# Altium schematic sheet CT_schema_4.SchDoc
size 527 x 503 mm
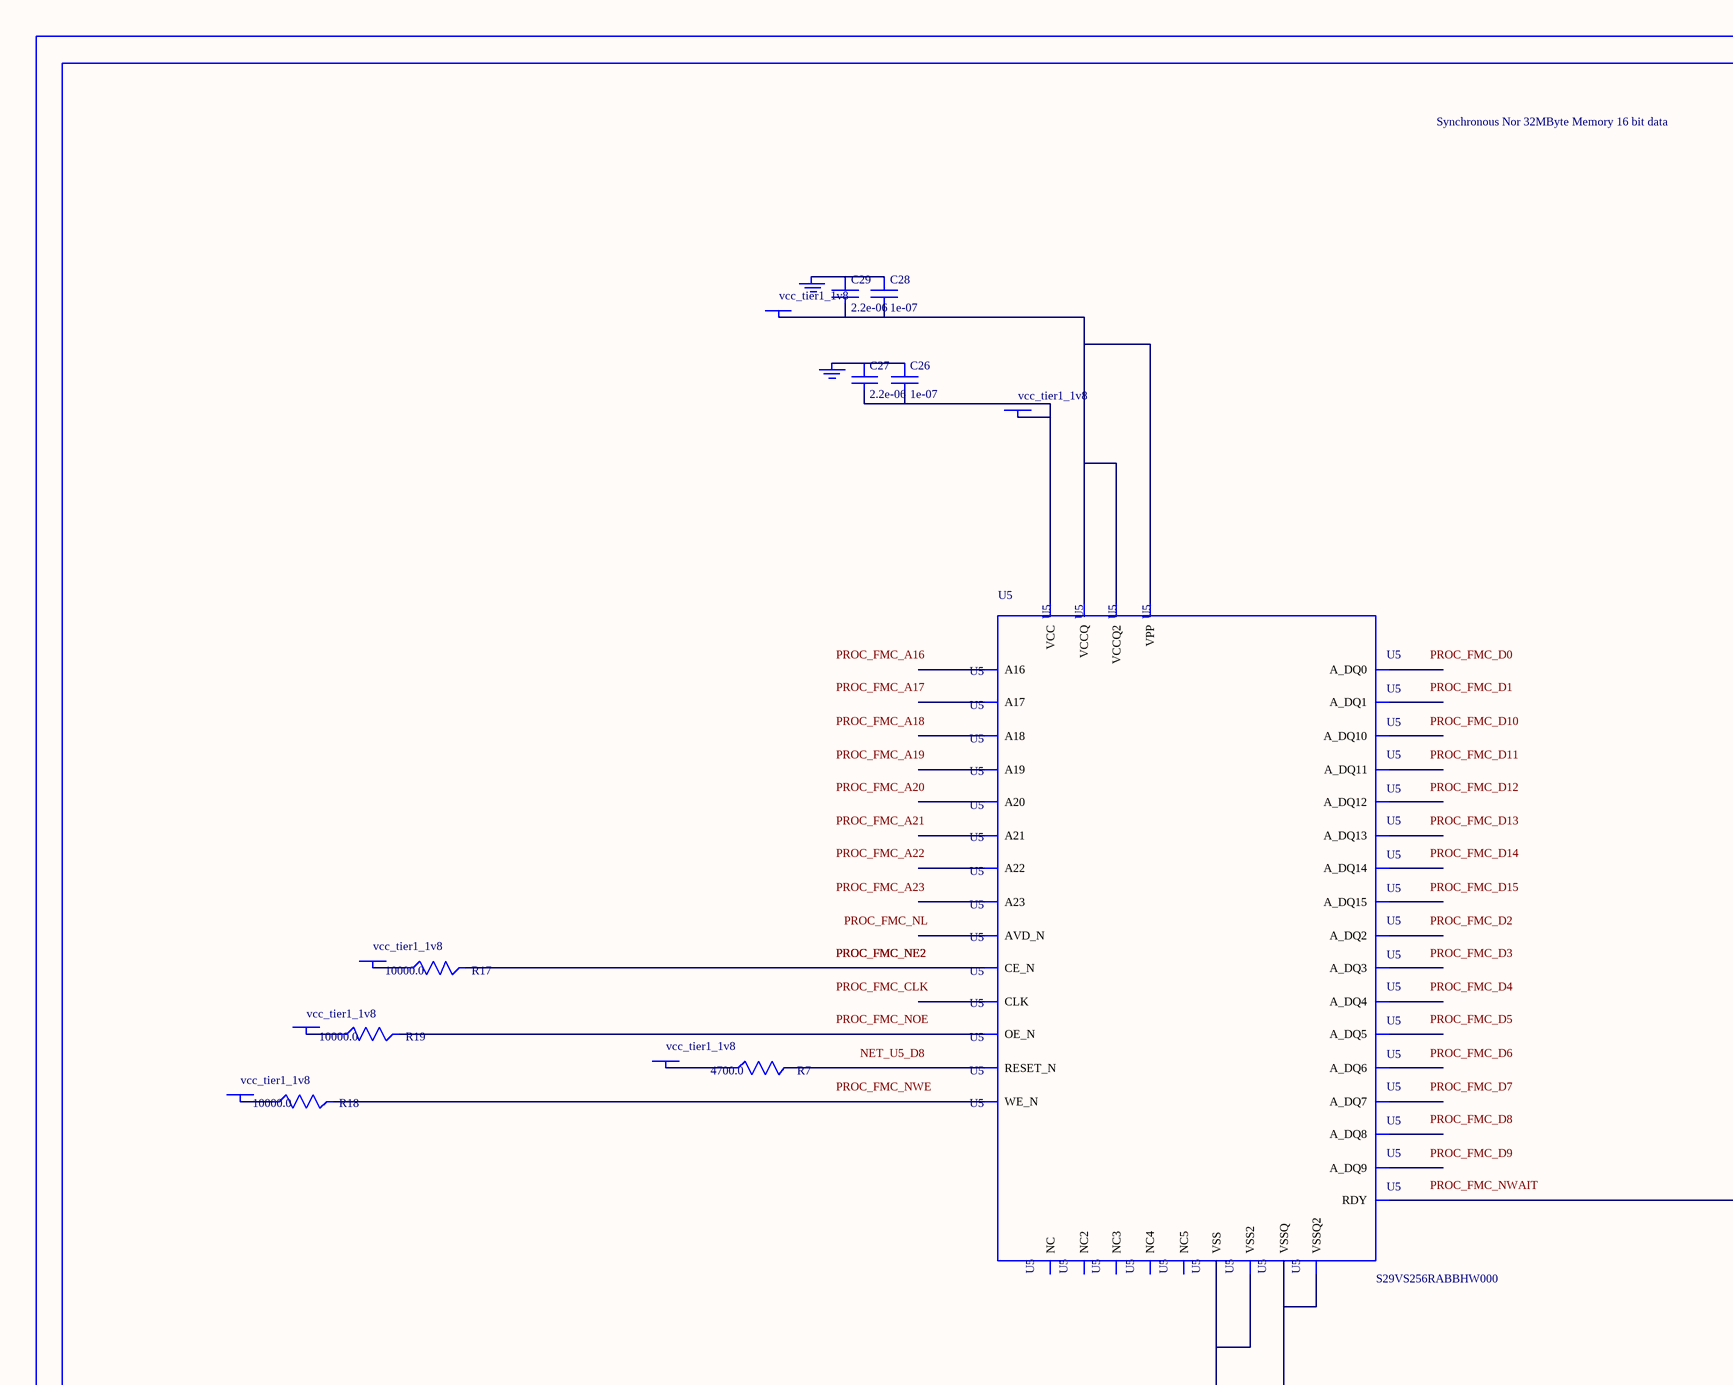
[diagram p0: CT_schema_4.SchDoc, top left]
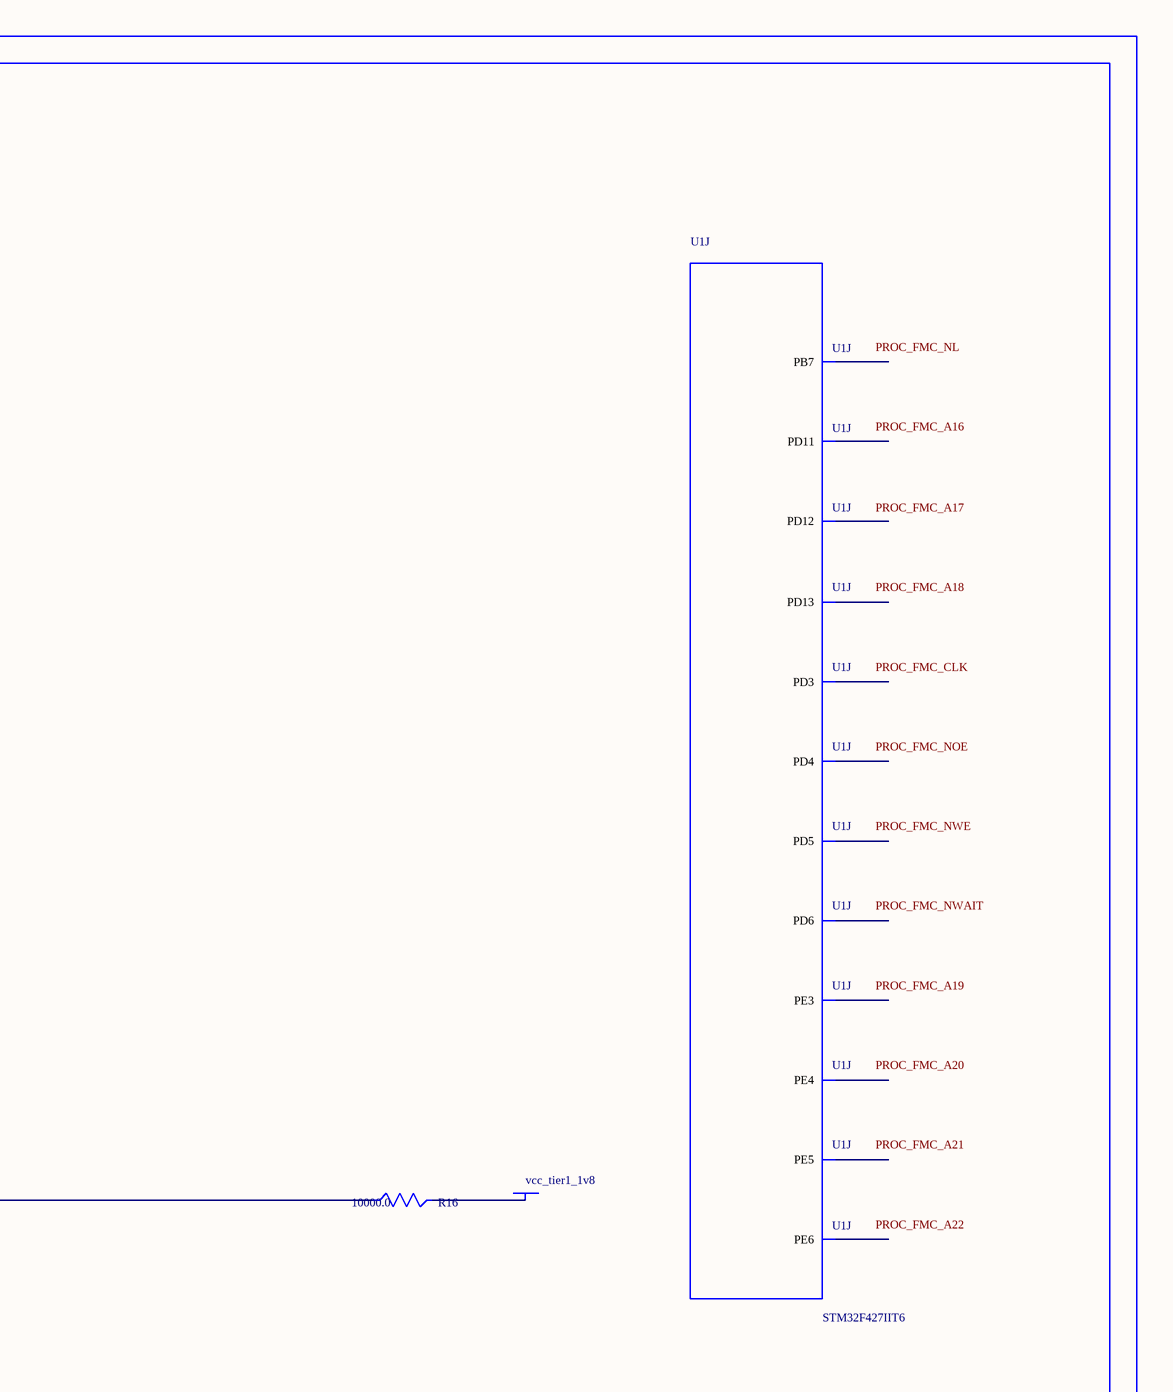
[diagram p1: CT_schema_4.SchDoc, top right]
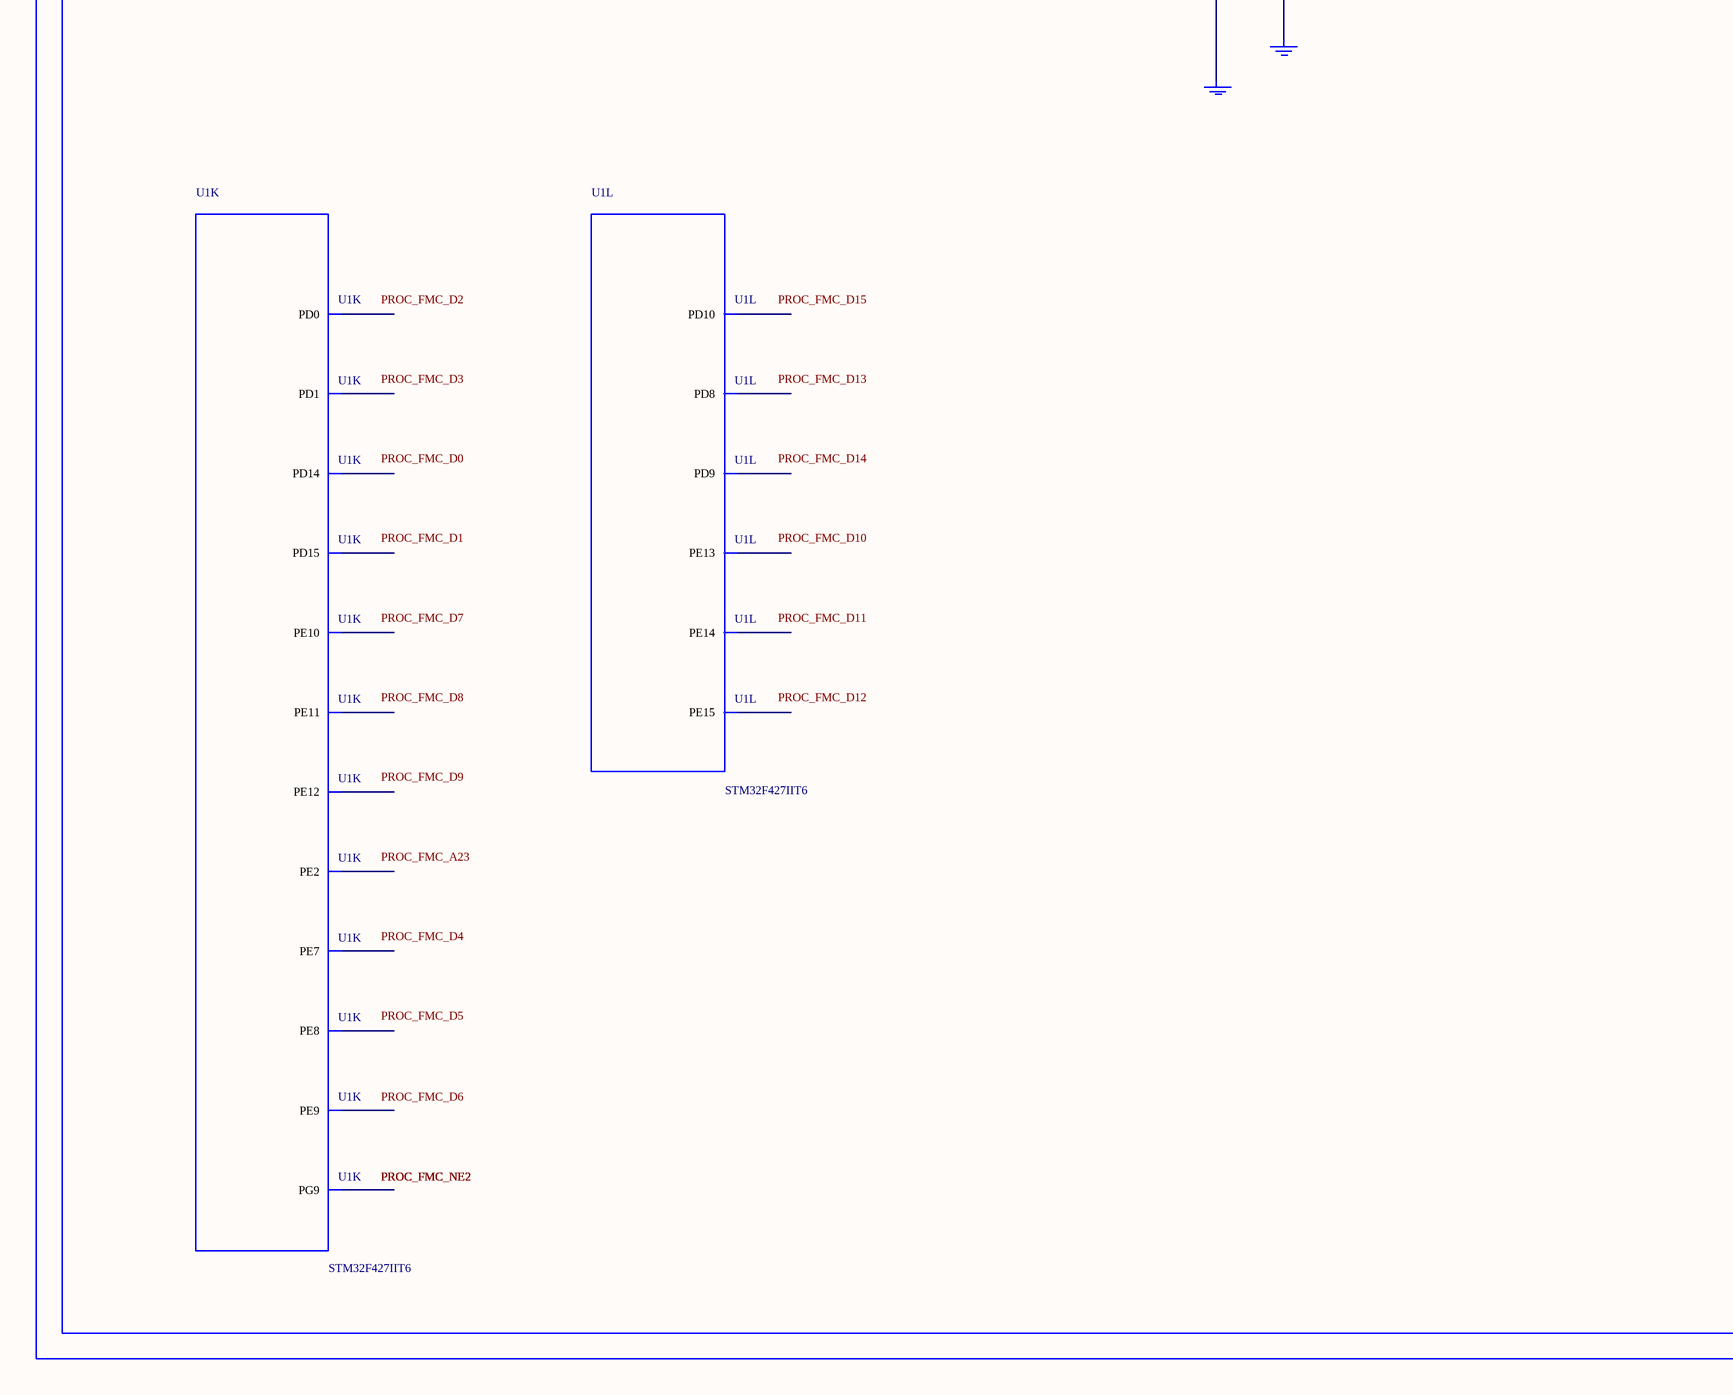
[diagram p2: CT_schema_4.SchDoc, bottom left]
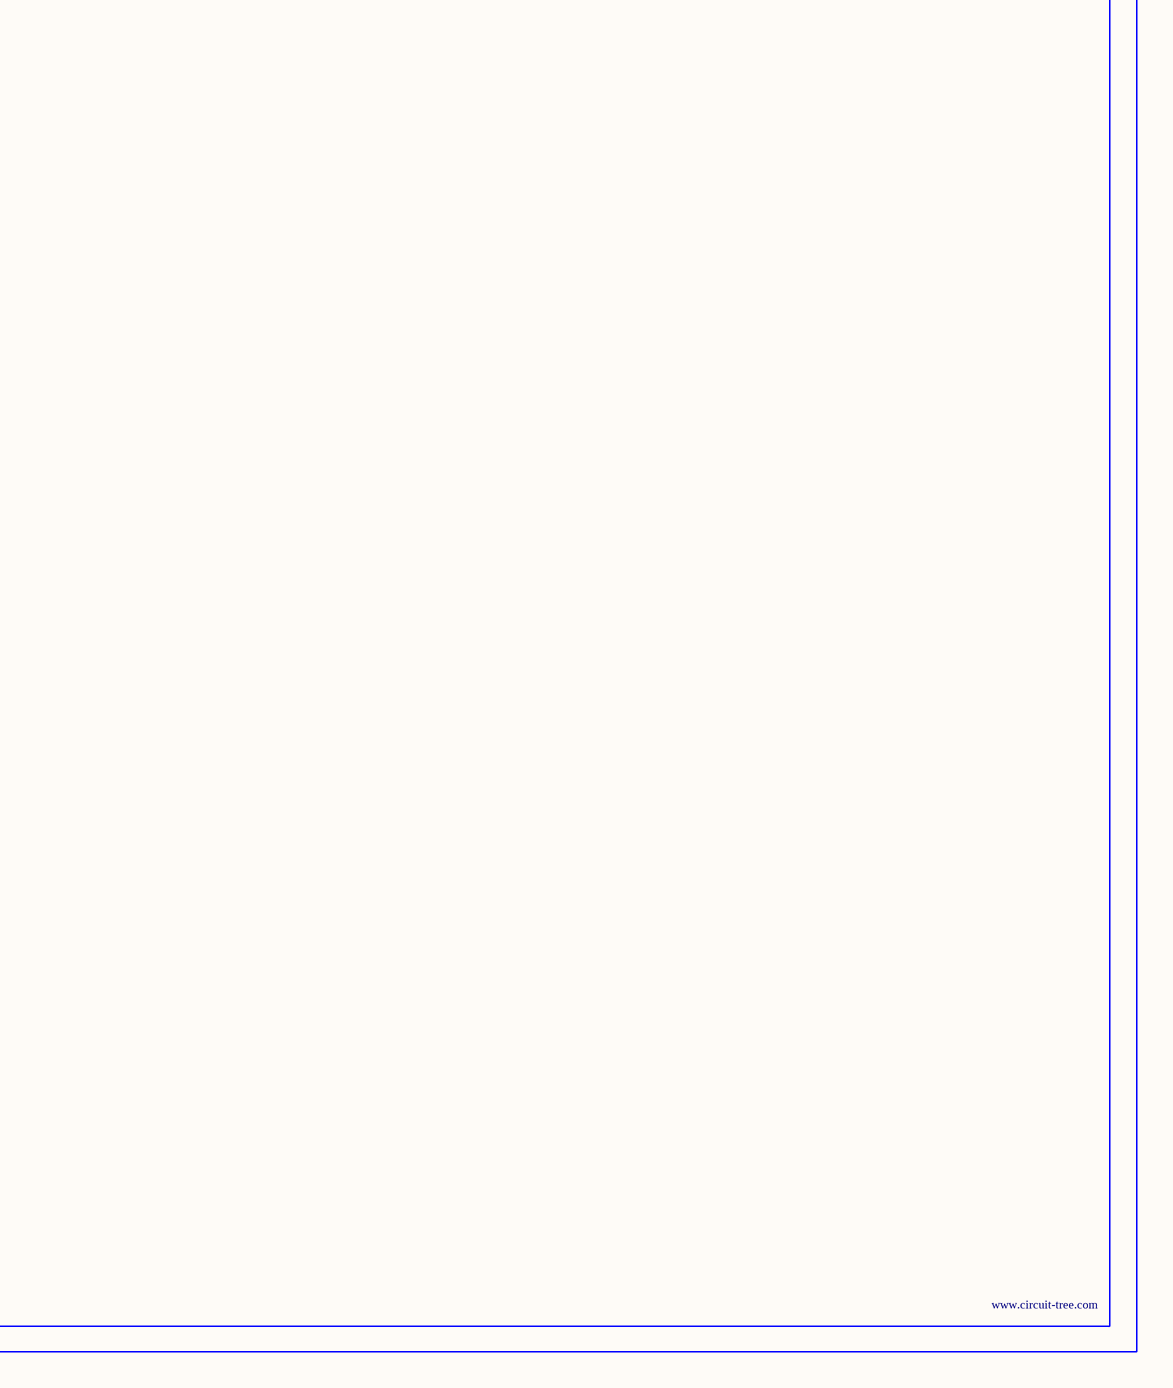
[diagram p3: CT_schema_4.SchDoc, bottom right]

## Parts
BORDER3  (no value)
C26  1e-07  [C0402]
C27  2.2e-06  [C0603]
C28  1e-07  [C0402]
C29  2.2e-06  [C0603]
GND_INSTANCE_3_0  (no value)
GND_INSTANCE_3_1  (no value)
GND_INSTANCE_3_2  (no value)
GND_INSTANCE_3_3  (no value)
POWER_INSTANCE_3_0  vcc_tier1_1v8
POWER_INSTANCE_3_1  vcc_tier1_1v8
POWER_INSTANCE_3_2  vcc_tier1_1v8
POWER_INSTANCE_3_3  vcc_tier1_1v8
POWER_INSTANCE_3_4  vcc_tier1_1v8
POWER_INSTANCE_3_5  vcc_tier1_1v8
POWER_INSTANCE_3_6  vcc_tier1_1v8
R7  4700.0  [R0603]
R16  10000.0  [R0603]
R17  10000.0  [R0603]
R18  10000.0  [R0603]
R19  10000.0  [R0603]
U1  STM32F427IIT6  [LQFP176]  (parts J,K,L of 14)
U5  S29VS256RABBHW000  [S29VS256RABBHW000]

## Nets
NetC26_1: C26.1 C27.1 GND_INSTANCE_3_0.0(GND)
NetC26_2: C26.2 C27.2 POWER_INSTANCE_3_0.0(PWR) U5.C7(VCC)
NetC28_1: C28.1 C29.1 GND_INSTANCE_3_1.0(GND)
NetC28_2: C28.2 C29.2 POWER_INSTANCE_3_1.0(PWR) U5.C9(VPP) U5.D3(VCCQ) U5.F10(VCCQ2)
NetGND_INSTANCE_3_2_0: GND_INSTANCE_3_2.0(GND) U5.C5(VSS) U5.D12(VSS2)
NetGND_INSTANCE_3_3_0: GND_INSTANCE_3_3.0(GND) U5.E3(VSSQ) U5.F5(VSSQ2)
NetPOWER_INSTANCE_3_2_0: POWER_INSTANCE_3_2.0(PWR) R16.2
NetPOWER_INSTANCE_3_3_0: POWER_INSTANCE_3_3.0(PWR) R17.1
NetPOWER_INSTANCE_3_4_0: POWER_INSTANCE_3_4.0(PWR) R18.1
NetPOWER_INSTANCE_3_5_0: POWER_INSTANCE_3_5.0(PWR) R19.1
NetPOWER_INSTANCE_3_6_0: POWER_INSTANCE_3_6.0(PWR) R7.1
NetR7_2: R7.2 U5.D8(RESET_N)
NetR16_1: R16.1 U5.C3(RDY)
NetR17_2: R17.2 U5.D11(CE_N)
NetR18_2: R18.2 U5.C8(WE_N)
NetR19_2: R19.2 U5.E12(OE_N)

Not connected (* = marked no-connect by the designer): U1 1(PE2) 2(PE3) 3(PE4) 4(PE5) 5(PE6) 68(PE7) 69(PE8) 70(PE9) 73(PE10) 74(PE11) 75(PE12) 76(PE13) 77(PE14) 78(PE15) 96(PD8) 97(PD9) 98(PD10) 99(PD11) 100(PD12) 101(PD13) 104(PD14) 105(PD15) 142(PD0) 143(PD1) 145(PD3) 146(PD4) 147(PD5) 150(PD6) 152(PG9) 165(PB7); U5 A1(NC) A14(NC2) C4(A21) C6(CLK) C10(A19) C11(A17) C12(A22) D4(A16) D5(A20) D6(AVD_N) D7(A23) D9(NC3) D10(A18) E4(A_DQ8) E5(A_DQ9) E6(A_DQ2) E7(A_DQ3) E8(A_DQ12) E9(A_DQ13) E10(A_DQ6) E11(A_DQ7) F3(A_DQ0) F4(A_DQ1) F6(A_DQ10) F7(A_DQ11) F8(A_DQ4) F9(A_DQ5) F11(A_DQ14) F12(A_DQ15) H1(NC4) H14(NC5)

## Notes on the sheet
- Labels drawn without touching a wire or pin: NET_U5_D8, PROC_FMC_A16, PROC_FMC_A17, PROC_FMC_A18, PROC_FMC_A19, PROC_FMC_A20, PROC_FMC_A21, PROC_FMC_A22, PROC_FMC_A23, PROC_FMC_CLK, PROC_FMC_D0, PROC_FMC_D1, PROC_FMC_D2, PROC_FMC_D3, PROC_FMC_D4, PROC_FMC_D5, PROC_FMC_D6, PROC_FMC_D7, PROC_FMC_D8, PROC_FMC_D9, PROC_FMC_D10, PROC_FMC_D11, PROC_FMC_D12, PROC_FMC_D13, PROC_FMC_D14, PROC_FMC_D15, PROC_FMC_NL, PROC_FMC_NOE, PROC_FMC_NWAIT, PROC_FMC_NWE

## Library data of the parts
BORDER3 = BORDER_PAGE3
C26 C28 = C0402C104K3RACTU
C27 C29 = C0603C225K8RACTU
GND_INSTANCE_3_0-GND_INSTANCE_3_3 = GND
POWER_INSTANCE_3_0-POWER_INSTANCE_3_6 = PWR
R7 = RC0603JR-074K7L
R16-R19 = RC0603JR-0710KL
